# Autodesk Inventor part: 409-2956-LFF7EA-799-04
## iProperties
Created: 2010-11
Part Number: 409-2956-LFF7EA-799-04
Material: 3/4" OD TUBE - SS
Document SubType Name: Modeling
Designer: S. Boerckel
Engineer: Steve Boerckel
Mass: 731.966 g
Surface Area: 1099.2 cm^2
Volume: 90.5898 cm^3
Density: 8.08 g/cm^3
Description: DRAIN TUBING
User Status: CUT/TUBE BEND
Length: 39.254 in
Author: S. Boerckel
Revision Number: 0
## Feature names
1. Sweep2
